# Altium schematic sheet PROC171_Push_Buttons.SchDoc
size 431 x 279 mm; Date: Not shown in title block; ApprovedBy: Not shown in title block; CheckedBy: Not shown in title block; Author: Not shown in title block; CompanyName: Not shown in title block; Engineer: Not shown in title block; Organization: Not shown in title block; Address1: Not shown in title block; Address2: Not shown in title block; Address3: Not shown in title block; Address4: Not shown in title block; DocumentNumber: 15; Revision: Use project parameter SCH_Rev; SheetNumber: 15; SheetTotal: 26; PageSetup: Record=PageOptions¦CenterHorizontal=True¦CenterVertical=True¦PrintScale=1.00¦XCorrection=1.00¦YCorrection=1.00¦PrintKind=0¦BorderSize=5000000¦LeftOffset=0¦BottomOffset=0¦Orientation=2¦PaperLength=1000¦PaperWidth=1000¦Scale=100¦PaperSource=15¦PrintQuality=600¦MediaType=1¦DitherType=10¦PaperKind=Letter¦PrintScaleMode=1
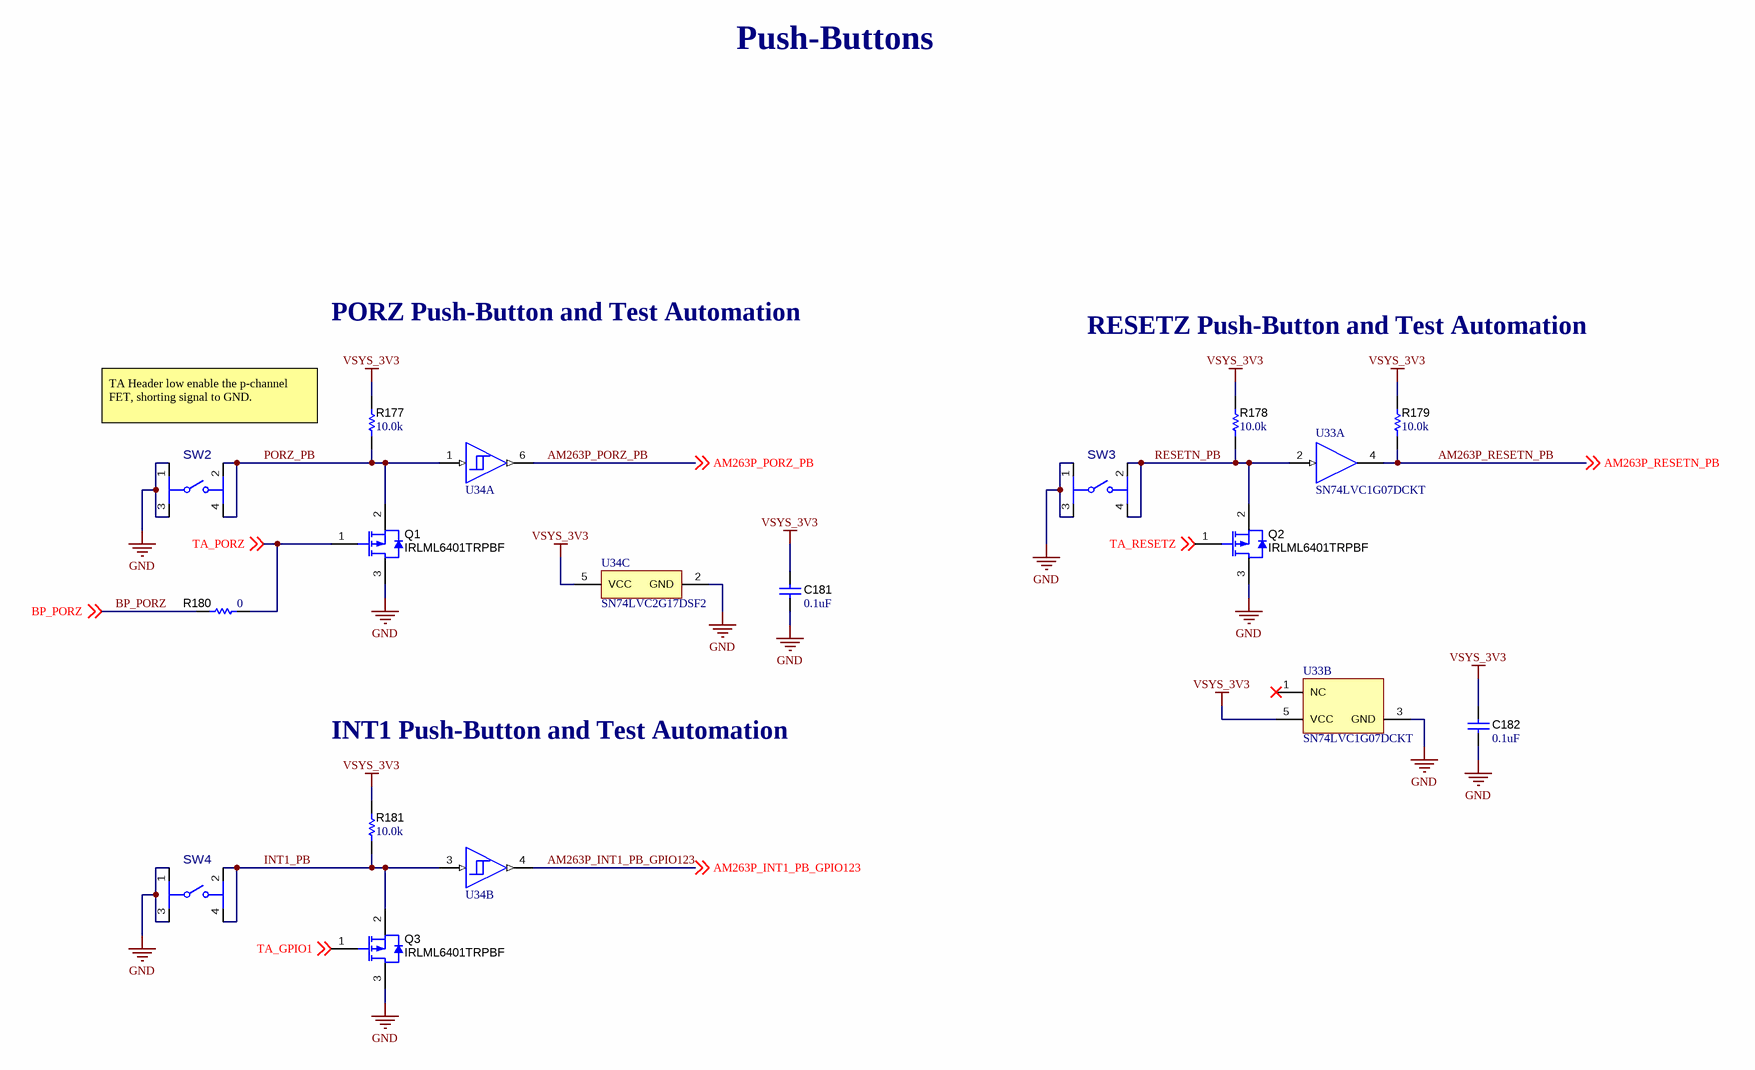
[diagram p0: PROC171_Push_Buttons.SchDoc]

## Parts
C181  ValueDisplayed: 0.1uF  [0402]  (hidden comment: GRM155R71E104KE14D)
C182  ValueDisplayed: 0.1uF  [0402]  (hidden comment: GRM155R71E104KE14D)
Q1  IRLML6401TRPBF  [SOT-23]
Q2  IRLML6401TRPBF  [SOT-23]
Q3  IRLML6401TRPBF  [SOT-23]
R177  ValueDisplayed: 10.0k  [0402]  (hidden comment: ERJ-2RKF1002X)
R178  ValueDisplayed: 10.0k  [0402]  (hidden comment: ERJ-2RKF1002X)
R179  ValueDisplayed: 10.0k  [0402]  (hidden comment: ERJ-2RKF1002X)
R180  ValueDisplayed: 0  [0402L]  (hidden comment: ERJ-2GE0R00X)
R181  ValueDisplayed: 10.0k  [0402]  (hidden comment: ERJ-2RKF1002X)
SW2  434351045816  [FP-434351045816_SMT_SW_4MM7_4MM5-MFG]  (value not drawn)
SW3  434351045816  [FP-434351045816_SMT_SW_4MM7_4MM5-MFG]  (value not drawn)
SW4  434351045816  [FP-434351045816_SMT_SW_4MM7_4MM5-MFG]  (value not drawn)
U33  SN74LVC1G07DCKT  [DCK0005A_N]  (parts A,B of 2)
U34  SN74LVC2G17DSF2  [DSF0006A]  (value not drawn)  (parts A,B,C of 3)

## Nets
GND: C181.1 C182.1 Q1.3(D) Q2.3(D) Q3.3(D) SW2.1 SW2.3 SW3.1 SW3.3 SW4.1 SW4.3 U33.3(GND) U34.2(GND)
VSYS_3V3: C181.2 C182.2 R177.2 R178.2 R179.2 R181.2 U33.5(VCC) U34.5(VCC)
AM263P_INT1_PB_GPIO123: U34.4(2Y) ; off-sheet AM263P_INT1_PB_GPIO123
AM263P_PORZ_PB: U34.6(1Y) ; off-sheet AM263P_PORZ_PB
AM263P_RESETN_PB: R179.1 U33.4(Y) ; off-sheet AM263P_RESETN_PB
BP_PORZ: R180.2 ; off-sheet BP_PORZ
INT1_PB: Q3.2(S) R181.1 SW4.2 SW4.4 U34.3(2A)
PORZ_PB: Q1.2(S) R177.1 SW2.2 SW2.4 U34.1(1A)
RESETN_PB: Q2.2(S) R178.1 SW3.2 SW3.4 U33.2(A)
TA_GPIO1: Q3.1(G) ; off-sheet TA_GPIO1
TA_PORZ: Q1.1(G) R180.1 ; off-sheet TA_PORZ
TA_RESETZ: Q2.1(G) ; off-sheet TA_RESETZ

Not connected (* = marked no-connect by the designer): U33 1(NC)*

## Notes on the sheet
- Push-Buttons
- PORZ Push-Button and Test Automation
- RESETZ Push-Button and Test Automation
- TA Header low enable the p-channel FET, shorting signal to GND.
- INT1 Push-Button and Test Automation

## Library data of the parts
C181 C182 = CMP-0006659-2: CAP, CERM, 0.1 uF, 25 V, +/- 10%, X7R, 0402; Manufacturer: MuRata; TaMin_C: -55°C; Polarized: N; SizeAreaWB_mm2: 3; U/M: EA; Value: 0.1uF; TaMax_C: 125°C; SizeZ_mm: 0.6; SizeX_mm: 1; SizeY_mm: 0.5; Value2: 25V; Cap_F: 100nF; AEC Category: Q200; Value1: Unknown
Q1-Q3 = CMP-0078819-2: MOSFET, P-CH, -12 V, -4.3 A, SOT-23; Alternate Manufacturer: None; Manufacturer: Infineon Technologies; SizeY_mm: 3; ChMode: Enhancement; SizeX_mm: 2.5; QgTyp_nC: 10; ChType: P; AEC Qualified: N; Value2: 10 nC; SizeZ_mm: 1.1; Green_Lifecycle: Active; Vgs_V: -8V; SizeArea_mm2: 7.5; Value: -12V; IdsMax_A: -4.3A; SizeAreaWB_mm2: 14; AEC Category: Q101; Value1: 0.05 ohm; Rdson45_ohm: 50m; Green_REACh: Passed
R177-R179 R181 = CMP-0026658-1: RES, 10.0 k, 1%, 0.1 W, 0402; Manufacturer: Panasonic; Power_W: 100mW; TempCo: 100 ppm/C; Value_Code: 10k0; U/M: EA; Value: 10.0k; EIA_Code: E96; Res_ohm: 10k; SizeX_mm: 1; SizeY_mm: 0.5; SizeZ_mm: 0.6; Value2: 0.1W; VDC_V: 50V; AEC Category: Q200
R180 = CMP-0026992-3: RES, 0, 5%, 0.1 W, AEC-Q200 Grade 0, 0402; Manufacturer: Panasonic; Power_W: 100mW; TempCo: 600 ppm/C; Value_Code: 0000; Value: 0; EIA_Code: E24; SizeX_mm: 1; SizeY_mm: 0.5; SizeZ_mm: 0.6; Value2: 0.1W; AEC Qualified: Y; VDC_V: 50V; AEC Category: Q200; SizeAreaWB_mm2: 3
SW2-SW4 = CMP-0093456-1: Tactile Switch SPST-NO Side Actuated Surface Mount, Right Angle; Manufacturer: Wurth Electronics; Operating Force: 160gf; SizeZ_mm: 1.75mm; AEC Qualified: No; Electromechanical Life: 200000Cycles; VDC_V: 12V; Contact Current Rating: 50mA; Coil Resistance_ohm: 100mΩ
U33 = CMP-0051392-2: Single Buffer/Driver With Open-Drain Output, DCK0005A, SMALL T&R; Manufacturer: Texas Instruments; Input Type: CMOS/TTL; F @ Nom Voltage(Max)(Mhz): 150; Technology Family: LVC; VCC(Min)(V): 1.65; 3-State Output: No; Rating: Catalog; Logic: True; ICC @ Nom Voltage(Max)(mA): 0.01; Bits(#): 1; VCC(Max)(V): 5.5; Sub-Family: Non-Inverting Buffer/Driver; Output Drive (IOL/IOH)(Max)(mA): 32/-32; tpd @ Nom Voltage(Max)(ns): 8.6,6,4.7,4; Output Type: CMOS; Voltage(Nom)(V): 1.8,2.5,3.3,5; AEC Category: Q200; AEC Qualified: N; CompType: IC; SizeAreaWB_mm2: 9.3; SizeArea_mm2: 4.2; SizeX_mm: 2.1; SizeY_mm: 2.0; SizeZ_mm: 1.1
U34 = CMP-0051904-4: Dual Schmitt-Trigger Buffer, DSF0006A, LARGE T&R; Manufacturer: Texas Instruments; Output Type: CMOS; Bits(#): 2; Input Type: CMOS/TTL; Technology Family: LVC; Schmitt Trigger: Yes; 3-State Output: No; VCC(Max)(V): 5.5; Sub-Family: Non-Inverting Buffer/Driver; Rating: Catalog; Output Drive (IOL/IOH)(Max)(mA): 32/-32; ICC @ Nom Voltage(Max)(mA): 0.01; VCC(Min)(V): 1.65; F @ Nom Voltage(Max)(Mhz): 150; Logic: True; Voltage(Nom)(V): 1.8,2.5,3.3,5; tpd @ Nom Voltage(Max)(ns): 9.3,5.7,5.4,4.3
